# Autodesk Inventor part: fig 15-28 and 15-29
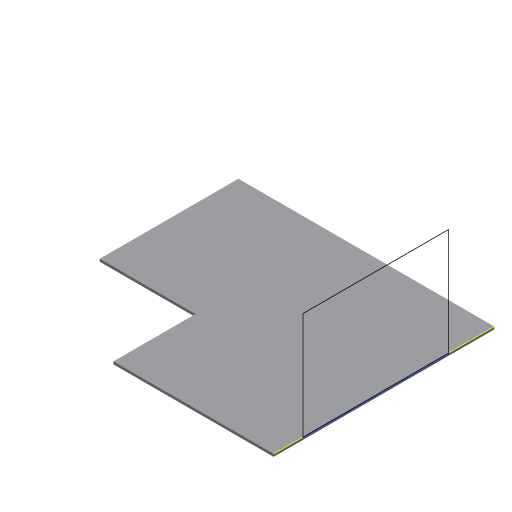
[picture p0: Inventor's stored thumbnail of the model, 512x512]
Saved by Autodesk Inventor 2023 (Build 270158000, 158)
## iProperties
Created: 2005-03
Part Number: fig 15-28 and 15-29
Document SubType Name: Sheet Metal
Designer: CADCIM
Manufacturer: Standard
Standards Organization: Custom
Density: 1 g/cm^3
Sheet Metal Rule: Default
Material: Generic
Appearance: Default
Author: CADCIM
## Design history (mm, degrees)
node "Face1"
  sketch "Sketch1"
    geometry: L1 (29.25, 32.25)-(-19.875, 32.25); L2 (-19.875, 32.25)-(-19.875, 5.625); L3 (-19.875, 5.625)-(-1.5, 5.625); L4 (-1.5, 5.625)-(-1.5, -10.125); L5 (-1.5, -10.125)-(29.25, -10.125); L6 (29.25, -10.125)-(29.25, 32.25)
    constraints: 12 end point, 4 parallel, 1 horizontal, 1 perpendicular
sketch "Sketch2"
  geometry: L1 (-0.5, 42.375)-(-0.5, 0) reference; L2 (-0.5, 5.593)-(-21.049, 5.593); L3 (-21.049, 5.593)-(-21.049, 33.56); L4 (-21.049, 33.56)-(-0.5, 33.56); L5 (-0.5, 33.56)-(-0.5, 5.593)
  constraints: 8 end point, 2 parallel, 1 horizontal, 1 perpendicular, 1 point on line
body "Solid1"
face "Plate1" dims "d1" = 0.5 (= Thickness)
other parameters: "Thickness" = 0.5, "BendRadius" = 0.5 (= Thickness), "BendReliefWidth" = 0.5 (= Thickness), "BendReliefDepth" = 0.25 (= 0.5 x Thickness), "CornerReliefSize" = 2 (= 4 x Thickness), "SeamGap" = 0.01, "MinimumRemnant" = 1 (= 2 x Thickness), "TransitionRadius" = 0.5 (= BendRadius), "d0" = 0.5 (= BendRadius), "JacobiRadiusSize" = 0.5 (= Thickness), "GapSize" = 0.5 (= Thickness)
